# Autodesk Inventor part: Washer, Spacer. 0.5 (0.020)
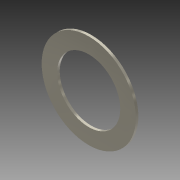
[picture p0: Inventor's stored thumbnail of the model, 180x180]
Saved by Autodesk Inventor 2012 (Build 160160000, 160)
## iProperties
Created: 2010-12
Part Number: Washer, Spacer. 0.5 (0.020)
Document SubType Name: Modeling
Designer: Alex
Density: 7.84 g/cm^3
Mass: 0.626604 g
Surface Area: 3.65413 cm^2
Volume: 0.079924 cm^3
Material: Steel, High Strength Low Alloy
Author: Alex
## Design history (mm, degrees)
sketch "Sketch1"
  geometry: C1 r 9.525 at (0, 0); 2 further points
  constraints: 1 centre point
  dimensions: "d0" = 19.05 diameter of C1
extrude "Extrusion1" new body sketch "Sketch1" distance "d1" = 0.508; taper "d2" = 0 deg
hole "Hole1" diameter "d5" = 12.7508; stored, may be unused: countersink angle "d9" = 82 deg, drill point angle "d11" = 118 deg; dims "d3" = 25.4, "d4" = 25.4, "d6" = 19.05, "d7" = 9.525, "d8" = 6.35, "d10" = 25.4
body "Solid1"
